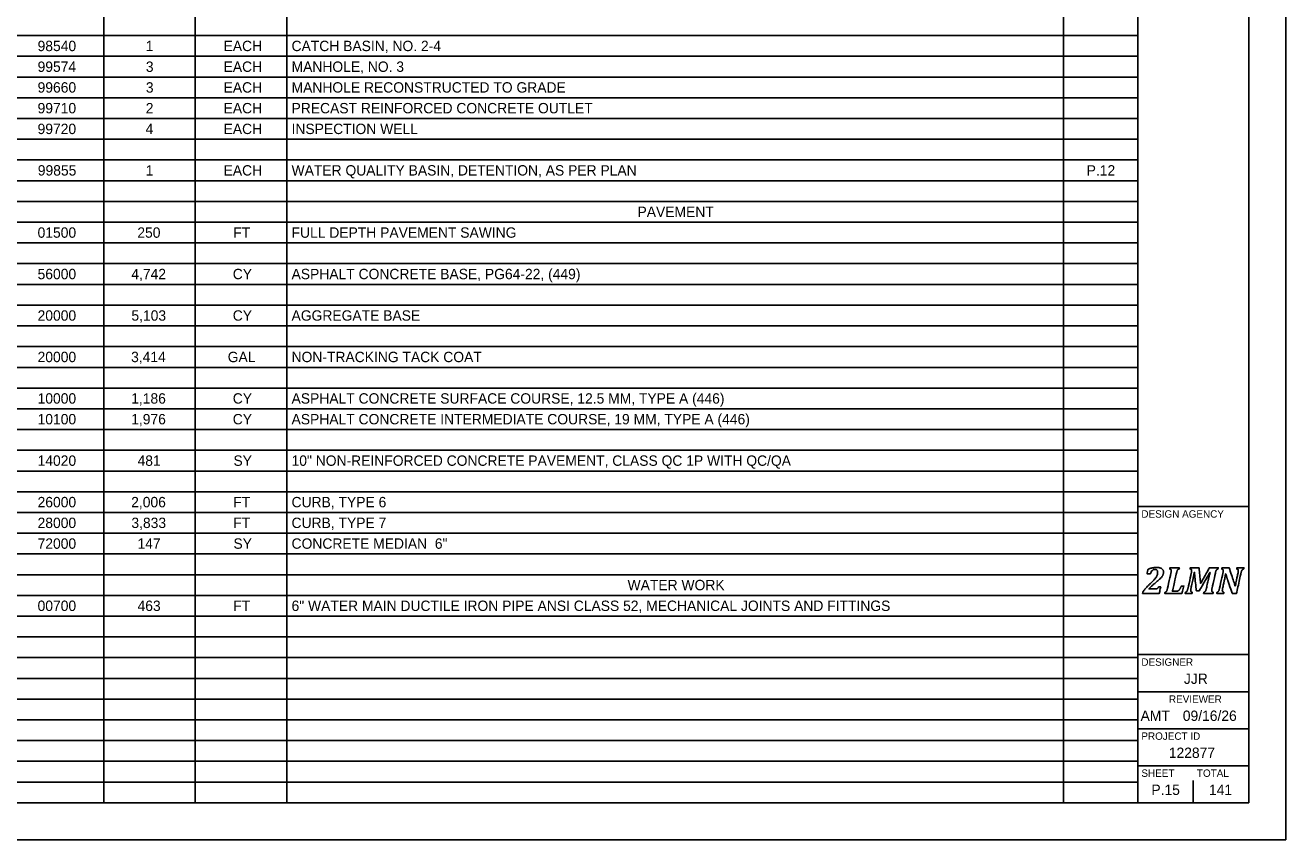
# Model space of a CAD drawing. Extents: x 0 to 34, y 0 to 22.
# Drawn here: x 16.98 to 34, y 0 to 11 of the extents above; entities that cross this region are included whole.
import ezdxf

# ---------------------------------------------------------------- set-up
doc = ezdxf.new("R2010")
doc.units = 0
for name, color, linetype in [('SH_Border', 7, 'Continuous'), ('SH_Cut_Line', 7, 'Continuous'), ('SH_Data', 7, 'Continuous'), ('SH_Text', 7, 'Continuous')]:
    doc.layers.add(name, color=color, linetype=linetype)

msp = doc.modelspace()

# ---------------------------------------------------------------- linework, layer by layer
at = {"layer": 'SH_Border'}
for p, q in [((32, 0.5), (32, 21.5)), ((32, 4.5), (33.5, 4.5)), ((32, 2.5), (33.5, 2.5)), ((32, 2), (33.5, 2)), ((32, 1.5), (33.5, 1.5)), ((32, 1), (33.5, 1))]:
    msp.add_line(p, q, dxfattribs=at)
msp.add_lwpolyline([(1.5, 21.5), (33.5, 21.5), (33.5, 0.5), (1.5, 0.5)], close=True, dxfattribs=at)
at = {"layer": 'SH_Cut_Line'}
msp.add_lwpolyline([(0, 0), (34, 0), (34, 22), (0, 22)], close=True, dxfattribs=at)
at = {"layer": 'SH_Data'}
for p, q in [((32.75, 3.5), (32.75, 3.5)), ((32.75, 0.5), (32.75, 0.8)), ((32.375, 0.675), (32.375, 0.675))]:
    msp.add_line(p, q, dxfattribs=at)
for points in [[(32.237, 3.388), (32.246, 3.388), (32.253, 3.389), (32.258, 3.39), (32.263, 3.392), (32.267, 3.394), (32.27, 3.397), (32.273, 3.401), (32.277, 3.408), (32.281, 3.417), (32.281, 3.417), (32.312, 3.417), (32.312, 3.417), (32.312, 3.417), (32.29, 3.326), (32.29, 3.326), (32.29, 3.326), (32.066, 3.326), (32.066, 3.326), (32.066, 3.326), (32.069, 3.343), (32.069, 3.343), (32.078, 3.358), (32.091, 3.375), (32.106, 3.394), (32.122, 3.412), (32.144, 3.435), (32.172, 3.462), (32.197, 3.486), (32.217, 3.506), (32.23, 3.521), (32.243, 3.537), (32.253, 3.551), (32.259, 3.566), (32.266, 3.58), (32.269, 3.595), (32.269, 3.61), (32.269, 3.622), (32.266, 3.632), (32.26, 3.64), (32.253, 3.647), (32.245, 3.65), (32.234, 3.65), (32.22, 3.65), (32.208, 3.646), (32.198, 3.636), (32.188, 3.627), (32.18, 3.613), (32.172, 3.593), (32.172, 3.593), (32.126, 3.593), (32.126, 3.593), (32.126, 3.593), (32.14, 3.654), (32.14, 3.654), (32.166, 3.663), (32.188, 3.669), (32.205, 3.673), (32.223, 3.676), (32.24, 3.678), (32.258, 3.678), (32.278, 3.678), (32.295, 3.675), (32.309, 3.669), (32.322, 3.664), (32.332, 3.656), (32.339, 3.646), (32.345, 3.637), (32.348, 3.626), (32.348, 3.613), (32.348, 3.602), (32.346, 3.591), (32.342, 3.581), (32.339, 3.571), (32.333, 3.56), (32.324, 3.549), (32.315, 3.539), (32.304, 3.526), (32.289, 3.513), (32.275, 3.499), (32.254, 3.482), (32.228, 3.46), (32.216, 3.45), (32.202, 3.438), (32.188, 3.425), (32.174, 3.412), (32.162, 3.4), (32.154, 3.391), (32.154, 3.391), (32.153, 3.388), (32.153, 3.388), (32.153, 3.388), (32.237, 3.388), (32.237, 3.388)], [(32.237, 3.388), (32.237, 3.388), (32.153, 3.388), (32.153, 3.388), (32.153, 3.388), (32.154, 3.391), (32.154, 3.391), (32.162, 3.4), (32.174, 3.412), (32.188, 3.425), (32.202, 3.438), (32.216, 3.45), (32.228, 3.46), (32.254, 3.482), (32.275, 3.499), (32.289, 3.513), (32.304, 3.526), (32.315, 3.539), (32.324, 3.549), (32.333, 3.56), (32.339, 3.571), (32.342, 3.581), (32.346, 3.591), (32.348, 3.602), (32.348, 3.613), (32.348, 3.626), (32.345, 3.637), (32.339, 3.646), (32.332, 3.656), (32.322, 3.664), (32.309, 3.669), (32.295, 3.675), (32.278, 3.678), (32.258, 3.678), (32.24, 3.678), (32.223, 3.676), (32.205, 3.673), (32.188, 3.669), (32.166, 3.663), (32.14, 3.654), (32.14, 3.654), (32.126, 3.593), (32.126, 3.593), (32.126, 3.593), (32.172, 3.593), (32.172, 3.593), (32.18, 3.613), (32.188, 3.627), (32.198, 3.636), (32.208, 3.646), (32.22, 3.65), (32.234, 3.65), (32.245, 3.65), (32.253, 3.647), (32.26, 3.64), (32.266, 3.632), (32.269, 3.622), (32.269, 3.61), (32.269, 3.595), (32.266, 3.58), (32.259, 3.566), (32.253, 3.551), (32.243, 3.537), (32.23, 3.521), (32.217, 3.506), (32.197, 3.486), (32.172, 3.462), (32.144, 3.435), (32.122, 3.412), (32.106, 3.394), (32.091, 3.375), (32.078, 3.358), (32.069, 3.343), (32.069, 3.343), (32.066, 3.326), (32.066, 3.326), (32.066, 3.326), (32.29, 3.326), (32.29, 3.326), (32.29, 3.326), (32.312, 3.417), (32.312, 3.417), (32.312, 3.417), (32.281, 3.417), (32.281, 3.417), (32.277, 3.408), (32.273, 3.401), (32.27, 3.397), (32.267, 3.394), (32.263, 3.392), (32.258, 3.39), (32.253, 3.389), (32.246, 3.388), (32.237, 3.388)], [(32.518, 3.356), (32.527, 3.356), (32.533, 3.357), (32.538, 3.358), (32.542, 3.36), (32.546, 3.362), (32.55, 3.365), (32.554, 3.368), (32.558, 3.372), (32.562, 3.377), (32.567, 3.382), (32.571, 3.388), (32.576, 3.397), (32.58, 3.405), (32.585, 3.415), (32.589, 3.427), (32.589, 3.427), (32.624, 3.427), (32.624, 3.427), (32.624, 3.427), (32.598, 3.326), (32.598, 3.326), (32.598, 3.326), (32.365, 3.326), (32.365, 3.326), (32.365, 3.326), (32.369, 3.343), (32.369, 3.343), (32.376, 3.345), (32.381, 3.348), (32.385, 3.351), (32.389, 3.355), (32.392, 3.36), (32.395, 3.366), (32.398, 3.373), (32.4, 3.382), (32.403, 3.395), (32.403, 3.395), (32.449, 3.605), (32.449, 3.605), (32.452, 3.615), (32.453, 3.625), (32.453, 3.635), (32.453, 3.642), (32.451, 3.647), (32.448, 3.651), (32.444, 3.654), (32.439, 3.656), (32.432, 3.657), (32.432, 3.657), (32.435, 3.674), (32.435, 3.674), (32.435, 3.674), (32.563, 3.674), (32.563, 3.674), (32.563, 3.674), (32.559, 3.657), (32.559, 3.657), (32.552, 3.655), (32.547, 3.652), (32.543, 3.649), (32.539, 3.645), (32.536, 3.64), (32.533, 3.634), (32.531, 3.627), (32.528, 3.618), (32.525, 3.605), (32.525, 3.605), (32.47, 3.356), (32.47, 3.356), (32.47, 3.356), (32.518, 3.356), (32.518, 3.356)], [(32.518, 3.356), (32.518, 3.356), (32.47, 3.356), (32.47, 3.356), (32.47, 3.356), (32.525, 3.605), (32.525, 3.605), (32.528, 3.618), (32.531, 3.627), (32.533, 3.634), (32.536, 3.64), (32.539, 3.645), (32.543, 3.649), (32.547, 3.652), (32.552, 3.655), (32.559, 3.657), (32.559, 3.657), (32.563, 3.674), (32.563, 3.674), (32.563, 3.674), (32.435, 3.674), (32.435, 3.674), (32.435, 3.674), (32.432, 3.657), (32.432, 3.657), (32.439, 3.656), (32.444, 3.654), (32.448, 3.651), (32.451, 3.647), (32.453, 3.642), (32.453, 3.635), (32.453, 3.625), (32.452, 3.615), (32.449, 3.605), (32.449, 3.605), (32.403, 3.395), (32.403, 3.395), (32.4, 3.382), (32.398, 3.373), (32.395, 3.366), (32.392, 3.36), (32.389, 3.355), (32.385, 3.351), (32.381, 3.348), (32.376, 3.345), (32.369, 3.343), (32.369, 3.343), (32.365, 3.326), (32.365, 3.326), (32.365, 3.326), (32.598, 3.326), (32.598, 3.326), (32.598, 3.326), (32.624, 3.427), (32.624, 3.427), (32.624, 3.427), (32.589, 3.427), (32.589, 3.427), (32.585, 3.415), (32.58, 3.405), (32.576, 3.397), (32.571, 3.388), (32.567, 3.382), (32.562, 3.377), (32.558, 3.372), (32.554, 3.368), (32.55, 3.365), (32.546, 3.362), (32.542, 3.36), (32.538, 3.358), (32.533, 3.357), (32.527, 3.356), (32.518, 3.356)], [(32.829, 3.674), (32.829, 3.674), (32.849, 3.461), (32.849, 3.461), (32.849, 3.461), (32.969, 3.674), (32.969, 3.674), (32.969, 3.674), (33.087, 3.674), (33.087, 3.674), (33.087, 3.674), (33.084, 3.657), (33.084, 3.657), (33.077, 3.655), (33.071, 3.652), (33.067, 3.649), (33.064, 3.645), (33.06, 3.64), (33.058, 3.634), (33.055, 3.627), (33.052, 3.618), (33.05, 3.605), (33.05, 3.605), (33.003, 3.395), (33.003, 3.395), (33.002, 3.39), (33.002, 3.387), (33.001, 3.384), (33.001, 3.382), (33.001, 3.379), (33, 3.376), (33, 3.373), (33, 3.369), (33, 3.365), (33, 3.358), (33.002, 3.353), (33.005, 3.349), (33.008, 3.346), (33.014, 3.344), (33.021, 3.343), (33.021, 3.343), (33.018, 3.326), (33.018, 3.326), (33.018, 3.326), (32.89, 3.326), (32.89, 3.326), (32.89, 3.326), (32.893, 3.343), (32.893, 3.343), (32.9, 3.345), (32.906, 3.348), (32.91, 3.351), (32.914, 3.355), (32.917, 3.36), (32.919, 3.366), (32.922, 3.373), (32.925, 3.382), (32.928, 3.395), (32.928, 3.395), (32.951, 3.502), (32.951, 3.502), (32.954, 3.513), (32.957, 3.529), (32.962, 3.548), (32.967, 3.568), (32.972, 3.588), (32.978, 3.609), (32.978, 3.609), (32.973, 3.609), (32.973, 3.609), (32.965, 3.594), (32.957, 3.579), (32.948, 3.563), (32.948, 3.563), (32.833, 3.364), (32.833, 3.364), (32.833, 3.364), (32.792, 3.364), (32.792, 3.364), (32.792, 3.364), (32.775, 3.518), (32.775, 3.518), (32.773, 3.537), (32.772, 3.554), (32.77, 3.569), (32.769, 3.583), (32.768, 3.597), (32.768, 3.611), (32.768, 3.611), (32.764, 3.611), (32.764, 3.611), (32.761, 3.596), (32.758, 3.578), (32.755, 3.558), (32.751, 3.538), (32.747, 3.521), (32.744, 3.507), (32.744, 3.507), (32.72, 3.395), (32.72, 3.395), (32.719, 3.39), (32.718, 3.387), (32.718, 3.384), (32.717, 3.382), (32.717, 3.379), (32.717, 3.376), (32.717, 3.373), (32.716, 3.369), (32.716, 3.365), (32.716, 3.358), (32.718, 3.353), (32.721, 3.349), (32.725, 3.346), (32.73, 3.344), (32.738, 3.343), (32.738, 3.343), (32.734, 3.326), (32.734, 3.326), (32.734, 3.326), (32.641, 3.326), (32.641, 3.326), (32.641, 3.326), (32.644, 3.343), (32.644, 3.343), (32.651, 3.345), (32.657, 3.348), (32.661, 3.351), (32.665, 3.355), (32.668, 3.36), (32.67, 3.366), (32.673, 3.373), (32.676, 3.382), (32.679, 3.395), (32.679, 3.395), (32.725, 3.605), (32.725, 3.605), (32.727, 3.615), (32.728, 3.625), (32.728, 3.635), (32.728, 3.642), (32.727, 3.647), (32.723, 3.651), (32.72, 3.654), (32.715, 3.656), (32.707, 3.657), (32.707, 3.657), (32.711, 3.674), (32.711, 3.674), (32.711, 3.674), (32.829, 3.674), (32.829, 3.674)], [(32.829, 3.674), (32.829, 3.674), (32.711, 3.674), (32.711, 3.674), (32.711, 3.674), (32.707, 3.657), (32.707, 3.657), (32.715, 3.656), (32.72, 3.654), (32.723, 3.651), (32.727, 3.647), (32.728, 3.642), (32.728, 3.635), (32.728, 3.625), (32.727, 3.615), (32.725, 3.605), (32.725, 3.605), (32.679, 3.395), (32.679, 3.395), (32.676, 3.382), (32.673, 3.373), (32.67, 3.366), (32.668, 3.36), (32.665, 3.355), (32.661, 3.351), (32.657, 3.348), (32.651, 3.345), (32.644, 3.343), (32.644, 3.343), (32.641, 3.326), (32.641, 3.326), (32.641, 3.326), (32.734, 3.326), (32.734, 3.326), (32.734, 3.326), (32.738, 3.343), (32.738, 3.343), (32.73, 3.344), (32.725, 3.346), (32.721, 3.349), (32.718, 3.353), (32.716, 3.358), (32.716, 3.365), (32.716, 3.369), (32.717, 3.373), (32.717, 3.376), (32.717, 3.379), (32.717, 3.382), (32.718, 3.384), (32.718, 3.387), (32.719, 3.39), (32.72, 3.395), (32.72, 3.395), (32.744, 3.507), (32.744, 3.507), (32.747, 3.521), (32.751, 3.538), (32.755, 3.558), (32.758, 3.578), (32.761, 3.596), (32.764, 3.611), (32.764, 3.611), (32.768, 3.611), (32.768, 3.611), (32.768, 3.597), (32.769, 3.583), (32.77, 3.569), (32.772, 3.554), (32.773, 3.537), (32.775, 3.518), (32.775, 3.518), (32.792, 3.364), (32.792, 3.364), (32.792, 3.364), (32.833, 3.364), (32.833, 3.364), (32.833, 3.364), (32.948, 3.563), (32.948, 3.563), (32.957, 3.579), (32.965, 3.594), (32.973, 3.609), (32.973, 3.609), (32.978, 3.609), (32.978, 3.609), (32.972, 3.588), (32.967, 3.568), (32.962, 3.548), (32.957, 3.529), (32.954, 3.513), (32.951, 3.502), (32.951, 3.502), (32.928, 3.395), (32.928, 3.395), (32.925, 3.382), (32.922, 3.373), (32.919, 3.366), (32.917, 3.36), (32.914, 3.355), (32.91, 3.351), (32.906, 3.348), (32.9, 3.345), (32.893, 3.343), (32.893, 3.343), (32.89, 3.326), (32.89, 3.326), (32.89, 3.326), (33.018, 3.326), (33.018, 3.326), (33.018, 3.326), (33.021, 3.343), (33.021, 3.343), (33.014, 3.344), (33.008, 3.346), (33.005, 3.349), (33.002, 3.353), (33, 3.358), (33, 3.365), (33, 3.369), (33, 3.373), (33, 3.376), (33.001, 3.379), (33.001, 3.382), (33.001, 3.384), (33.002, 3.387), (33.002, 3.39), (33.003, 3.395), (33.003, 3.395), (33.05, 3.605), (33.05, 3.605), (33.052, 3.618), (33.055, 3.627), (33.058, 3.634), (33.06, 3.64), (33.064, 3.645), (33.067, 3.649), (33.071, 3.652), (33.077, 3.655), (33.084, 3.657), (33.084, 3.657), (33.087, 3.674), (33.087, 3.674), (33.087, 3.674), (32.969, 3.674), (32.969, 3.674), (32.969, 3.674), (32.849, 3.461), (32.849, 3.461), (32.849, 3.461), (32.829, 3.674), (32.829, 3.674)], [(33.137, 3.674), (33.137, 3.674), (33.234, 3.674), (33.234, 3.674), (33.234, 3.674), (33.283, 3.53), (33.283, 3.53), (33.296, 3.49), (33.307, 3.456), (33.315, 3.426), (33.315, 3.426), (33.318, 3.426), (33.318, 3.426), (33.323, 3.455), (33.329, 3.488), (33.337, 3.523), (33.337, 3.523), (33.355, 3.605), (33.355, 3.605), (33.357, 3.615), (33.358, 3.625), (33.358, 3.635), (33.358, 3.642), (33.357, 3.647), (33.353, 3.651), (33.35, 3.654), (33.345, 3.656), (33.337, 3.657), (33.337, 3.657), (33.341, 3.674), (33.341, 3.674), (33.341, 3.674), (33.434, 3.674), (33.434, 3.674), (33.434, 3.674), (33.431, 3.657), (33.431, 3.657), (33.424, 3.655), (33.418, 3.652), (33.414, 3.649), (33.41, 3.645), (33.407, 3.64), (33.405, 3.634), (33.402, 3.627), (33.399, 3.618), (33.396, 3.605), (33.396, 3.605), (33.335, 3.326), (33.335, 3.326), (33.335, 3.326), (33.277, 3.326), (33.277, 3.326), (33.277, 3.326), (33.216, 3.504), (33.216, 3.504), (33.211, 3.518), (33.207, 3.531), (33.204, 3.543), (33.2, 3.556), (33.195, 3.571), (33.19, 3.59), (33.19, 3.59), (33.186, 3.59), (33.186, 3.59), (33.185, 3.579), (33.182, 3.563), (33.179, 3.543), (33.175, 3.523), (33.17, 3.501), (33.165, 3.478), (33.165, 3.478), (33.147, 3.395), (33.147, 3.395), (33.146, 3.39), (33.145, 3.387), (33.145, 3.384), (33.144, 3.382), (33.144, 3.379), (33.144, 3.376), (33.143, 3.373), (33.143, 3.369), (33.143, 3.365), (33.143, 3.358), (33.145, 3.353), (33.148, 3.349), (33.152, 3.346), (33.157, 3.344), (33.164, 3.343), (33.164, 3.343), (33.161, 3.326), (33.161, 3.326), (33.161, 3.326), (33.067, 3.326), (33.067, 3.326), (33.067, 3.326), (33.071, 3.343), (33.071, 3.343), (33.078, 3.345), (33.083, 3.348), (33.087, 3.351), (33.091, 3.355), (33.094, 3.36), (33.097, 3.366), (33.1, 3.373), (33.102, 3.382), (33.105, 3.395), (33.105, 3.395), (33.151, 3.605), (33.151, 3.605), (33.154, 3.615), (33.155, 3.625), (33.155, 3.635), (33.155, 3.642), (33.153, 3.647), (33.15, 3.651), (33.146, 3.654), (33.141, 3.656), (33.134, 3.657), (33.134, 3.657), (33.137, 3.674), (33.137, 3.674)], [(33.137, 3.674), (33.137, 3.674), (33.134, 3.657), (33.134, 3.657), (33.141, 3.656), (33.146, 3.654), (33.15, 3.651), (33.153, 3.647), (33.155, 3.642), (33.155, 3.635), (33.155, 3.625), (33.154, 3.615), (33.151, 3.605), (33.151, 3.605), (33.105, 3.395), (33.105, 3.395), (33.102, 3.382), (33.1, 3.373), (33.097, 3.366), (33.094, 3.36), (33.091, 3.355), (33.087, 3.351), (33.083, 3.348), (33.078, 3.345), (33.071, 3.343), (33.071, 3.343), (33.067, 3.326), (33.067, 3.326), (33.067, 3.326), (33.161, 3.326), (33.161, 3.326), (33.161, 3.326), (33.164, 3.343), (33.164, 3.343), (33.157, 3.344), (33.152, 3.346), (33.148, 3.349), (33.145, 3.353), (33.143, 3.358), (33.143, 3.365), (33.143, 3.369), (33.143, 3.373), (33.144, 3.376), (33.144, 3.379), (33.144, 3.382), (33.145, 3.384), (33.145, 3.387), (33.146, 3.39), (33.147, 3.395), (33.147, 3.395), (33.165, 3.478), (33.165, 3.478), (33.17, 3.501), (33.175, 3.523), (33.179, 3.543), (33.182, 3.563), (33.185, 3.579), (33.186, 3.59), (33.186, 3.59), (33.19, 3.59), (33.19, 3.59), (33.195, 3.571), (33.2, 3.556), (33.204, 3.543), (33.207, 3.531), (33.211, 3.518), (33.216, 3.504), (33.216, 3.504), (33.277, 3.326), (33.277, 3.326), (33.277, 3.326), (33.335, 3.326), (33.335, 3.326), (33.335, 3.326), (33.396, 3.605), (33.396, 3.605), (33.399, 3.618), (33.402, 3.627), (33.405, 3.634), (33.407, 3.64), (33.41, 3.645), (33.414, 3.649), (33.418, 3.652), (33.424, 3.655), (33.431, 3.657), (33.431, 3.657), (33.434, 3.674), (33.434, 3.674), (33.434, 3.674), (33.341, 3.674), (33.341, 3.674), (33.341, 3.674), (33.337, 3.657), (33.337, 3.657), (33.345, 3.656), (33.35, 3.654), (33.353, 3.651), (33.357, 3.647), (33.358, 3.642), (33.358, 3.635), (33.358, 3.625), (33.357, 3.615), (33.355, 3.605), (33.355, 3.605), (33.337, 3.523), (33.337, 3.523), (33.329, 3.488), (33.323, 3.455), (33.318, 3.426), (33.318, 3.426), (33.315, 3.426), (33.315, 3.426), (33.307, 3.456), (33.296, 3.49), (33.283, 3.53), (33.283, 3.53), (33.234, 3.674), (33.234, 3.674), (33.234, 3.674), (33.137, 3.674), (33.137, 3.674)]]:
    msp.add_open_spline(points, degree=3, dxfattribs=at)
at = {"layer": 'SH_Text'}
for p, q in [((18.036, 21.5), (18.036, 0.5)), ((19.272, 21.5), (19.272, 0.5)), ((20.507, 21.5), (20.507, 0.5)), ((30.999, 21.5), (30.999, 0.5)), ((32.004, 21.5), (32.004, 0.5)), ((1.5, 10.86), (32.004, 10.86)), ((1.5, 10.58), (32.004, 10.58)), ((1.5, 10.3), (32.004, 10.3)), ((1.5, 10.02), (32.004, 10.02)), ((1.5, 9.74), (32.004, 9.74)), ((1.5, 9.46), (32.004, 9.46)), ((1.5, 9.18), (32.004, 9.18)), ((1.5, 8.9), (32.004, 8.9)), ((1.5, 8.62), (32.004, 8.62)), ((1.5, 8.34), (32.004, 8.34)), ((1.5, 8.06), (32.004, 8.06)), ((1.5, 7.78), (32.004, 7.78)), ((1.5, 7.5), (32.004, 7.5)), ((1.5, 7.22), (32.004, 7.22)), ((1.5, 6.94), (32.004, 6.94)), ((1.5, 6.66), (32.004, 6.66)), ((1.5, 6.38), (32.004, 6.38)), ((1.5, 6.1), (32.004, 6.1)), ((1.5, 5.82), (32.004, 5.82)), ((1.5, 5.54), (32.004, 5.54)), ((1.5, 5.26), (32.004, 5.26)), ((1.5, 4.98), (32.004, 4.98)), ((1.5, 4.7), (32.004, 4.7)), ((1.5, 4.42), (32.004, 4.42)), ((1.5, 4.14), (32.004, 4.14)), ((1.5, 3.86), (32.004, 3.86)), ((1.5, 3.58), (32.004, 3.58)), ((1.5, 3.3), (32.004, 3.3)), ((1.5, 3.02), (32.004, 3.02)), ((1.5, 2.74), (32.004, 2.74)), ((1.5, 2.46), (32.004, 2.46)), ((1.5, 2.18), (32.004, 2.18)), ((1.5, 1.9), (32.004, 1.9)), ((1.5, 1.62), (32.004, 1.62)), ((1.5, 1.34), (32.004, 1.34)), ((1.5, 1.06), (32.004, 1.06)), ((1.5, 0.78), (32.004, 0.78)), ((1.5, 0.5), (32.004, 0.5))]:
    msp.add_line(p, q, dxfattribs=at)

# ---------------------------------------------------------------- texts
at = {"layer": 'SH_Data'}
for s, height, p in [('DESIGN AGENCY', 0.1, (32.05, 4.35)), ('DESIGNER', 0.1, (32.05, 2.35)), ('JJR', 0.14, (32.624, 2.105)), ('REVIEWER', 0.1, (32.422, 1.85)), ('AMT', 0.14, (32.039, 1.605)), ('09/16/26', 0.14, (32.609, 1.605)), ('PROJECT ID', 0.1, (32.05, 1.35)), ('122877', 0.14, (32.42, 1.105)), ('SHEET', 0.1, (32.05, 0.85)), ('TOTAL', 0.1, (32.8, 0.85)), ('P.15', 0.14, (32.185, 0.605)), ('141', 0.14, (32.963, 0.605))]:
    msp.add_text(s, height=height, dxfattribs=at).set_placement(p)
at = {"layer": 'SH_Text'}
for s, p in [('98540', (17.143, 10.65)), ('1', (18.604, 10.65)), ('EACH', (19.655, 10.65)), ('CATCH BASIN, NO. 2-4', (20.573, 10.65)), ('99574', (17.143, 10.37)), ('3', (18.605, 10.37)), ('EACH', (19.655, 10.37)), ('MANHOLE, NO. 3', (20.573, 10.37)), ('99660', (17.143, 10.09)), ('3', (18.605, 10.09)), ('EACH', (19.655, 10.09)), ('MANHOLE RECONSTRUCTED TO GRADE', (20.573, 10.09)), ('99710', (17.143, 9.81)), ('2', (18.604, 9.81)), ('EACH', (19.655, 9.81)), ('PRECAST REINFORCED CONCRETE OUTLET', (20.573, 9.81)), ('99720', (17.143, 9.53)), ('4', (18.601, 9.53)), ('EACH', (19.655, 9.53)), ('INSPECTION WELL', (20.573, 9.53)), ('99855', (17.146, 8.97)), ('1', (18.604, 8.97)), ('EACH', (19.655, 8.97)), ('WATER QUALITY BASIN, DETENTION, AS PER PLAN', (20.573, 8.97)), ('P.12', (31.311, 8.97)), ('PAVEMENT', (25.245, 8.41)), ('01500', (17.143, 8.13)), ('250', (18.49, 8.13)), ('FT', (19.786, 8.13)), ('FULL DEPTH PAVEMENT SAWING', (20.573, 8.13)), ('56000', (17.143, 7.57)), ('4,742', (18.409, 7.57)), ('CY', (19.779, 7.57)), ('ASPHALT CONCRETE BASE, PG64-22, (449)', (20.573, 7.57)), ('20000', (17.143, 7.01)), ('5,103', (18.41, 7.01)), ('CY', (19.779, 7.01)), ('AGGREGATE BASE', (20.573, 7.01)), ('20000', (17.143, 6.45)), ('3,414', (18.406, 6.45)), ('GAL', (19.711, 6.45)), ('NON-TRACKING TACK COAT', (20.573, 6.45)), ('10000', (17.143, 5.89)), ('1,186', (18.407, 5.89)), ('CY', (19.779, 5.89)), ('ASPHALT CONCRETE SURFACE COURSE, 12.5 MM, TYPE A (446)', (20.573, 5.89)), ('10100', (17.143, 5.61)), ('1,976', (18.407, 5.61)), ('CY', (19.779, 5.61)), ('ASPHALT CONCRETE INTERMEDIATE COURSE, 19 MM, TYPE A (446)', (20.573, 5.61)), ('14020', (17.143, 5.05)), ('481', (18.493, 5.05)), ('SY', (19.788, 5.05)), ('10" NON-REINFORCED CONCRETE PAVEMENT, CLASS QC 1P WITH QC/QA', (20.573, 5.05)), ('26000', (17.143, 4.49)), ('2,006', (18.407, 4.49)), ('FT', (19.786, 4.49)), ('CURB, TYPE 6', (20.573, 4.49)), ('28000', (17.143, 4.21)), ('3,833', (18.41, 4.21)), ('FT', (19.786, 4.21)), ('CURB, TYPE 7', (20.573, 4.21)), ('72000', (17.143, 3.93)), ('147', (18.492, 3.93)), ('SY', (19.788, 3.93)), ('CONCRETE MEDIAN  6"', (20.573, 3.93)), ('WATER WORK', (25.111, 3.37)), ('00700', (17.143, 3.09)), ('463', (18.493, 3.09)), ('FT', (19.786, 3.09)), ('6" WATER MAIN DUCTILE IRON PIPE ANSI CLASS 52, MECHANICAL JOINTS AND FITTINGS', (20.573, 3.09))]:
    msp.add_text(s, height=0.14, dxfattribs=at).set_placement(p)

doc.saveas('drawing.dxf')
